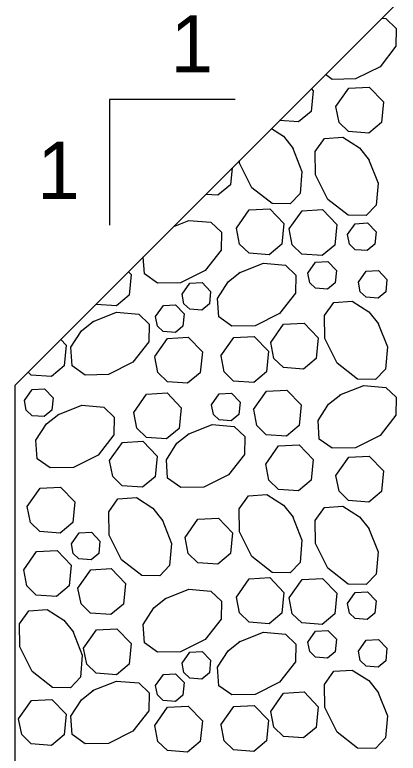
# Model space of a CAD drawing. Extents: x 638079 to 640019, y 297691 to 298879.
# Drawn here: x 639448.62 to 639468.71, y 298517.23 to 298555.89 of the extents above; entities that cross this region are included whole.
import ezdxf

# ---------------------------------------------------------------- set-up
doc = ezdxf.new("R2010")
doc.units = 0
doc.layers.add('1', color=7, linetype='Continuous')

msp = doc.modelspace()

# ---------------------------------------------------------------- linework, layer by layer
at = {"layer": '1'}
for p, q in [((639448.623, 298536.485), (639468.941, 298556.803)), ((639453.58, 298551.456), (639453.58, 298544.871)), ((639460.165, 298551.456), (639453.58, 298551.456)), ((639448.623, 298536.485), (639448.623, 298506.005))]:
    msp.add_line(p, q, dxfattribs=at)
for points in [[(639467.856, 298555.718), (639468.062, 298555.7), (639468.611, 298555.178), (639468.594, 298554.241), (639467.761, 298553.175), (639466.473, 298552.531), (639465.259, 298552.51), (639464.902, 298552.764)], [(639464.161, 298552.023), (639464.262, 298551.918), (639464.154, 298550.834), (639463.491, 298550.282), (639462.492, 298550.355)], [(639465.446, 298551.088), (639466.118, 298552.044), (639467.192, 298552.106), (639467.938, 298551.332), (639467.83, 298550.248), (639467.167, 298549.696), (639466.107, 298549.773), (639465.609, 298550.257), (639465.447, 298551.088)], [(639462.071, 298549.934), (639462.695, 298549.534), (639463.202, 298548.899)], [(639467.155, 298548.339), (639467.654, 298547.082), (639467.554, 298545.926), (639467.032, 298545.377), (639466.095, 298545.395), (639465.029, 298546.228), (639464.386, 298547.516), (639464.364, 298548.73), (639464.85, 298549.413), (639465.816, 298549.478), (639466.681, 298548.924), (639467.188, 298548.289)], [(639463.17, 298548.949), (639463.668, 298547.692), (639463.568, 298546.536), (639463.046, 298545.987), (639462.109, 298546.005), (639461.044, 298546.838), (639460.4, 298548.126), (639460.397, 298548.26)], [(639460.017, 298547.879), (639459.929, 298546.995), (639459.266, 298546.444), (639458.627, 298546.49)], [(639460.235, 298544.718), (639460.907, 298545.674), (639461.981, 298545.735), (639462.727, 298544.962), (639462.619, 298543.878), (639461.956, 298543.326), (639460.896, 298543.403), (639460.398, 298543.886), (639460.236, 298544.717)], [(639463.001, 298544.677), (639463.673, 298545.633), (639464.746, 298545.695), (639465.493, 298544.921), (639465.385, 298543.837), (639464.721, 298543.285), (639463.662, 298543.362), (639463.163, 298543.846), (639463.001, 298544.677)], [(639456.953, 298544.816), (639457.743, 298545.129), (639458.898, 298545.029), (639459.447, 298544.507), (639459.43, 298543.569), (639458.596, 298542.504), (639457.308, 298541.86), (639456.095, 298541.839), (639455.411, 298542.324), (639455.352, 298543.214)], [(639466.06, 298544.382), (639466.463, 298544.955), (639467.107, 298544.992), (639467.555, 298544.528), (639467.49, 298543.878), (639467.092, 298543.547), (639466.456, 298543.593), (639466.157, 298543.883), (639466.06, 298544.381)], [(639460.387, 298542.384), (639461.645, 298542.882), (639462.8, 298542.782), (639463.349, 298542.26), (639463.332, 298541.323), (639462.498, 298540.257), (639461.21, 298539.614), (639459.997, 298539.592), (639459.313, 298540.078), (639459.249, 298541.045), (639459.803, 298541.909), (639460.438, 298542.416)], [(639463.979, 298542.364), (639464.382, 298542.938), (639465.026, 298542.975), (639465.474, 298542.51), (639465.409, 298541.86), (639465.011, 298541.529), (639464.375, 298541.575), (639464.076, 298541.865), (639463.979, 298542.364)], [(639454.578, 298542.44), (639454.723, 298542.289), (639454.615, 298541.205), (639453.952, 298540.654), (639452.892, 298540.73), (639452.88, 298540.742)], [(639466.627, 298541.891), (639467.03, 298542.465), (639467.674, 298542.502), (639468.122, 298542.037), (639468.057, 298541.387), (639467.66, 298541.056), (639467.024, 298541.102), (639466.724, 298541.392), (639466.627, 298541.891)], [(639457.39, 298541.261), (639457.794, 298541.835), (639458.438, 298541.871), (639458.885, 298541.407), (639458.821, 298540.757), (639458.423, 298540.426), (639457.787, 298540.472), (639457.488, 298540.762), (639457.391, 298541.261)], [(639467.643, 298539.758), (639468.142, 298538.5), (639468.042, 298537.345), (639467.52, 298536.796), (639466.582, 298536.813), (639465.517, 298537.647), (639464.873, 298538.935), (639464.852, 298540.148), (639465.337, 298540.832), (639466.304, 298540.896), (639467.169, 298540.342), (639467.675, 298539.707)], [(639456.003, 298540.094), (639456.407, 298540.668), (639457.051, 298540.705), (639457.498, 298540.241), (639457.434, 298539.59), (639457.036, 298539.259), (639456.4, 298539.305), (639456.101, 298539.595), (639456.004, 298540.094)], [(639452.701, 298539.822), (639453.959, 298540.32), (639455.114, 298540.22), (639455.663, 298539.698), (639455.646, 298538.761), (639454.812, 298537.696), (639453.525, 298537.052), (639452.311, 298537.03), (639451.628, 298537.516), (639451.563, 298538.483), (639452.117, 298539.347), (639452.752, 298539.854)], [(639462.034, 298538.733), (639462.706, 298539.69), (639463.78, 298539.751), (639464.526, 298538.977), (639464.418, 298537.893), (639463.755, 298537.342), (639462.695, 298537.419), (639462.197, 298537.902), (639462.035, 298538.733)], [(639451.028, 298538.89), (639451.316, 298538.591), (639451.208, 298537.507), (639450.545, 298536.956), (639449.485, 298537.032), (639449.325, 298537.188)], [(639455.958, 298537.993), (639456.631, 298538.949), (639457.704, 298539.01), (639458.45, 298538.237), (639458.342, 298537.152), (639457.679, 298536.601), (639456.619, 298536.678), (639456.121, 298537.161), (639455.959, 298537.992)], [(639459.427, 298538.032), (639460.099, 298538.988), (639461.173, 298539.05), (639461.919, 298538.276), (639461.811, 298537.192), (639461.148, 298536.64), (639460.088, 298536.717), (639459.589, 298537.201), (639459.428, 298538.032)], [(639449.131, 298535.691), (639449.534, 298536.265), (639450.178, 298536.301), (639450.626, 298535.837), (639450.561, 298535.187), (639450.163, 298534.856), (639449.527, 298534.902), (639449.228, 298535.192), (639449.131, 298535.691)], [(639461.138, 298535.222), (639461.81, 298536.179), (639462.884, 298536.24), (639463.63, 298535.466), (639463.522, 298534.382), (639462.859, 298533.831), (639461.799, 298533.907), (639461.3, 298534.391), (639461.139, 298535.222)], [(639465.649, 298535.987), (639466.907, 298536.485), (639468.062, 298536.386), (639468.611, 298535.864), (639468.594, 298534.926), (639467.761, 298533.861), (639466.473, 298533.217), (639465.259, 298533.196), (639464.576, 298533.681), (639464.511, 298534.648), (639465.065, 298535.513), (639465.7, 298536.019)], [(639454.856, 298535.077), (639455.528, 298536.033), (639456.601, 298536.095), (639457.348, 298535.321), (639457.24, 298534.237), (639456.577, 298533.685), (639455.517, 298533.762), (639455.018, 298534.246), (639454.856, 298535.077)], [(639458.935, 298535.47), (639459.338, 298536.044), (639459.982, 298536.081), (639460.43, 298535.616), (639460.365, 298534.966), (639459.968, 298534.635), (639459.331, 298534.681), (639459.032, 298534.971), (639458.935, 298535.47)], [(639450.873, 298534.954), (639452.13, 298535.453), (639453.286, 298535.353), (639453.835, 298534.831), (639453.817, 298533.894), (639452.984, 298532.828), (639451.696, 298532.184), (639450.482, 298532.163), (639449.799, 298532.649), (639449.734, 298533.615), (639450.289, 298534.48), (639450.924, 298534.987)], [(639457.705, 298533.938), (639458.963, 298534.436), (639460.118, 298534.336), (639460.667, 298533.814), (639460.65, 298532.877), (639459.816, 298531.812), (639458.528, 298531.168), (639457.315, 298531.146), (639456.631, 298531.632), (639456.567, 298532.599), (639457.121, 298533.463), (639457.756, 298533.97)], [(639453.591, 298532.547), (639454.263, 298533.503), (639455.336, 298533.565), (639456.083, 298532.791), (639455.975, 298531.707), (639455.312, 298531.155), (639454.252, 298531.232), (639453.753, 298531.716), (639453.591, 298532.547)], [(639461.771, 298532.359), (639462.443, 298533.316), (639463.516, 298533.377), (639464.262, 298532.603), (639464.154, 298531.519), (639463.491, 298530.968), (639462.432, 298531.044), (639461.933, 298531.528), (639461.771, 298532.359)], [(639465.446, 298531.774), (639466.118, 298532.73), (639467.192, 298532.791), (639467.938, 298532.018), (639467.83, 298530.934), (639467.167, 298530.382), (639466.107, 298530.459), (639465.609, 298530.942), (639465.447, 298531.773)], [(639449.28, 298530.147), (639449.952, 298531.104), (639451.025, 298531.165), (639451.772, 298530.391), (639451.664, 298529.307), (639451.001, 298528.756), (639449.941, 298528.832), (639449.442, 298529.316), (639449.28, 298530.147)], [(639463.17, 298529.635), (639463.668, 298528.377), (639463.568, 298527.222), (639463.046, 298526.673), (639462.109, 298526.69), (639461.044, 298527.524), (639460.4, 298528.812), (639460.378, 298530.025), (639460.864, 298530.709), (639461.831, 298530.773), (639462.695, 298530.219), (639463.202, 298529.584)], [(639456.337, 298529.472), (639456.836, 298528.215), (639456.736, 298527.059), (639456.214, 298526.51), (639455.276, 298526.528), (639454.211, 298527.361), (639453.567, 298528.649), (639453.546, 298529.863), (639454.031, 298530.546), (639454.998, 298530.61), (639455.863, 298530.056), (639456.369, 298529.421)], [(639467.155, 298529.025), (639467.654, 298527.767), (639467.554, 298526.612), (639467.032, 298526.063), (639466.095, 298526.08), (639465.029, 298526.914), (639464.386, 298528.202), (639464.364, 298529.415), (639464.85, 298530.099), (639465.816, 298530.163), (639466.681, 298529.609), (639467.188, 298528.974)], [(639457.545, 298528.521), (639458.217, 298529.477), (639459.29, 298529.538), (639460.037, 298528.765), (639459.929, 298527.681), (639459.266, 298527.129), (639458.206, 298527.206), (639457.707, 298527.689), (639457.545, 298528.521)], [(639451.59, 298528.188), (639451.993, 298528.762), (639452.637, 298528.799), (639453.085, 298528.334), (639453.02, 298527.684), (639452.622, 298527.353), (639451.986, 298527.399), (639451.687, 298527.689), (639451.59, 298528.188)], [(639449.092, 298526.827), (639449.764, 298527.783), (639450.837, 298527.844), (639451.583, 298527.071), (639451.475, 298525.986), (639450.812, 298525.435), (639449.752, 298525.512), (639449.254, 298525.995), (639449.092, 298526.826)], [(639451.932, 298525.877), (639452.605, 298526.833), (639453.678, 298526.895), (639454.424, 298526.121), (639454.316, 298525.037), (639453.653, 298524.485), (639452.593, 298524.562), (639452.095, 298525.046), (639451.933, 298525.877)], [(639460.235, 298525.403), (639460.907, 298526.36), (639461.981, 298526.421), (639462.727, 298525.647), (639462.619, 298524.563), (639461.956, 298524.012), (639460.896, 298524.088), (639460.398, 298524.572), (639460.236, 298525.403)], [(639463.001, 298525.362), (639463.673, 298526.319), (639464.746, 298526.38), (639465.493, 298525.606), (639465.385, 298524.522), (639464.721, 298523.971), (639463.662, 298524.048), (639463.163, 298524.531), (639463.001, 298525.362)], [(639456.485, 298525.316), (639457.743, 298525.814), (639458.898, 298525.714), (639459.447, 298525.192), (639459.43, 298524.255), (639458.596, 298523.19), (639457.308, 298522.546), (639456.095, 298522.524), (639455.411, 298523.01), (639455.347, 298523.977), (639455.901, 298524.841), (639456.536, 298525.348)], [(639466.06, 298525.067), (639466.463, 298525.641), (639467.107, 298525.678), (639467.555, 298525.213), (639467.49, 298524.563), (639467.092, 298524.232), (639466.456, 298524.278), (639466.157, 298524.568), (639466.06, 298525.067)], [(639451.66, 298523.616), (639452.159, 298522.358), (639452.059, 298521.203), (639451.537, 298520.654), (639450.599, 298520.671), (639449.534, 298521.505), (639448.89, 298522.792), (639448.869, 298524.006), (639449.354, 298524.689), (639450.321, 298524.754), (639451.186, 298524.2), (639451.692, 298523.565)], [(639452.231, 298522.731), (639452.904, 298523.687), (639453.977, 298523.748), (639454.723, 298522.975), (639454.615, 298521.891), (639453.952, 298521.339), (639452.892, 298521.416), (639452.394, 298521.899), (639452.232, 298522.731)], [(639460.387, 298523.069), (639461.645, 298523.568), (639462.8, 298523.468), (639463.349, 298522.946), (639463.332, 298522.008), (639462.498, 298520.943), (639461.21, 298520.299), (639459.997, 298520.278), (639459.313, 298520.763), (639459.249, 298521.73), (639459.803, 298522.595), (639460.438, 298523.101)], [(639463.979, 298523.049), (639464.382, 298523.623), (639465.026, 298523.66), (639465.474, 298523.196), (639465.409, 298522.545), (639465.011, 298522.214), (639464.375, 298522.261), (639464.076, 298522.551), (639463.979, 298523.049)], [(639466.627, 298522.577), (639467.03, 298523.15), (639467.674, 298523.187), (639468.122, 298522.723), (639468.057, 298522.073), (639467.66, 298521.742), (639467.024, 298521.788), (639466.724, 298522.078), (639466.627, 298522.576)], [(639457.39, 298521.946), (639457.794, 298522.52), (639458.438, 298522.557), (639458.885, 298522.093), (639458.821, 298521.442), (639458.423, 298521.111), (639457.787, 298521.157), (639457.488, 298521.447), (639457.391, 298521.946)], [(639467.643, 298520.443), (639468.142, 298519.186), (639468.042, 298518.03), (639467.52, 298517.481), (639466.582, 298517.499), (639465.517, 298518.332), (639464.873, 298519.62), (639464.852, 298520.834), (639465.337, 298521.517), (639466.304, 298521.582), (639467.169, 298521.028), (639467.675, 298520.393)], [(639456.003, 298520.78), (639456.407, 298521.354), (639457.051, 298521.39), (639457.498, 298520.926), (639457.434, 298520.276), (639457.036, 298519.945), (639456.4, 298519.991), (639456.101, 298520.281), (639456.004, 298520.78)], [(639452.701, 298520.507), (639453.959, 298521.006), (639455.114, 298520.906), (639455.663, 298520.384), (639455.646, 298519.446), (639454.812, 298518.381), (639453.525, 298517.737), (639452.311, 298517.716), (639451.628, 298518.201), (639451.563, 298519.168), (639452.117, 298520.033), (639452.752, 298520.539)], [(639462.034, 298519.419), (639462.706, 298520.375), (639463.78, 298520.437), (639464.526, 298519.663), (639464.418, 298518.579), (639463.755, 298518.027), (639462.695, 298518.104), (639462.197, 298518.588), (639462.035, 298519.419)], [(639448.824, 298519.033), (639449.497, 298519.989), (639450.57, 298520.05), (639451.316, 298519.277), (639451.208, 298518.193), (639450.545, 298517.641), (639449.485, 298517.718), (639448.987, 298518.201), (639448.825, 298519.033)], [(639455.958, 298518.678), (639456.631, 298519.634), (639457.704, 298519.696), (639458.45, 298518.922), (639458.342, 298517.838), (639457.679, 298517.286), (639456.619, 298517.363), (639456.121, 298517.847), (639455.959, 298518.678)], [(639459.427, 298518.718), (639460.099, 298519.674), (639461.173, 298519.735), (639461.919, 298518.962), (639461.811, 298517.877), (639461.148, 298517.326), (639460.088, 298517.403), (639459.589, 298517.886), (639459.428, 298518.717)]]:
    msp.add_lwpolyline(points, dxfattribs=at)

# ---------------------------------------------------------------- texts
for p in [(639456.786, 298552.872), (639449.796, 298546.242)]:
    msp.add_text('1', height=3, dxfattribs=at).set_placement(p)

doc.saveas('drawing.dxf')
